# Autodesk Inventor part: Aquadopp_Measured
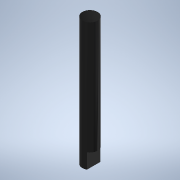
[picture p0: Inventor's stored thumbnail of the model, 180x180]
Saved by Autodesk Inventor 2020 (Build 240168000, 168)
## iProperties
Created: 2020-09
Part Number: Aquadopp_Measured
Material: Acetal Resin, Black
Document SubType Name: Modeling
Designer: biggshj
Manufacturer: Standard
Standards Organization: Custom
Density: 0.800062 g/cm^3
Appearance: Smooth - Black
Mass: 2247.5 g
Surface Area: 1595.65 cm^2
Volume: 2809.16 cm^3
Company: NIWA Instrument Systems
Author: biggshj
Revision Number: 1
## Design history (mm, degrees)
sketch "Sketch1"
  geometry: C1 r 38 at (0, 0); 1 further point
  constraints: 1 centre point, 1 coincident
  dimensions: "d0" = 76 diameter of C1
extrude "Extrusion1" new body sketch "Sketch1" distance "d1" = 635; taper "d2" = 0 deg
sketch "Sketch2"
  geometry: L1 (38, 0)-(-38, 0) reference; L2 (-38, 0)-(-18, 0); L3 (-18, 0)-(-18, 75); L4 (-18, 75)-(-38, 75); L5 (-38, 75)-(-38, 0); 2 further points
  constraints: 8 end point, 2 parallel, 1 horizontal, 1 perpendicular
  dimensions: "d3" = 75 distance of L4.end L1.end; "d4" = 20 distance of L3.end L4.end
extrude "Extrusion2" cut sketch "Sketch2" stored distance "d5" = 635; taper "d6" = 0 deg
body "Solid1"
